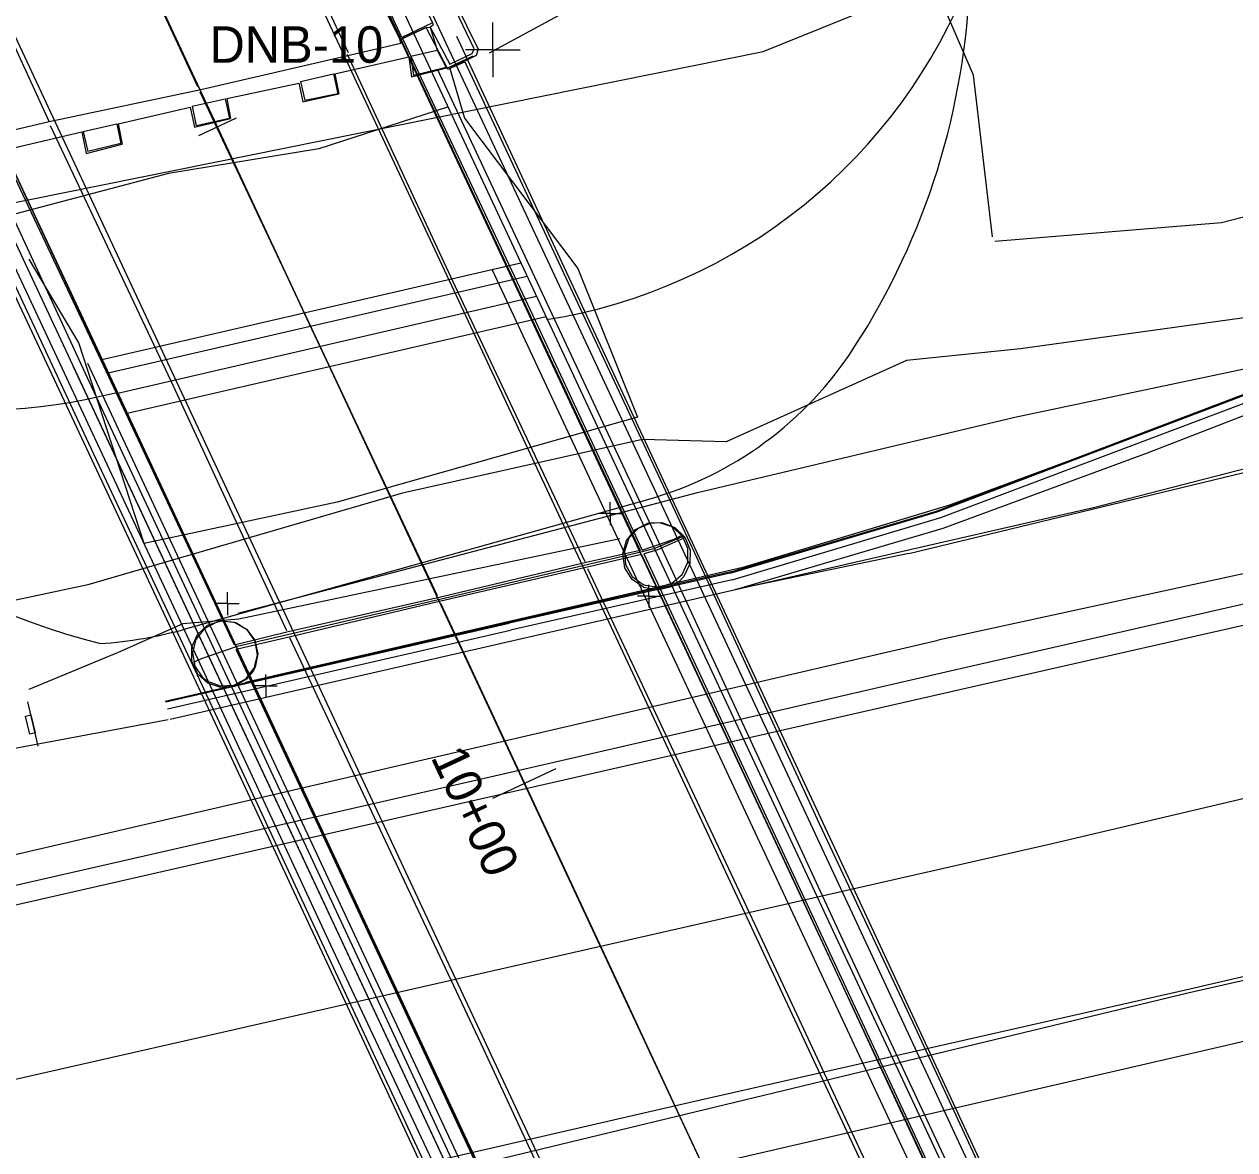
# Model space of a CAD drawing. Extents: x 1040567 to 1041254, y 1126791 to 1127594.
# Drawn here: x 1040909 to 1040992.5, y 1127190.9 to 1127268.5 of the extents above; entities that cross this region are included whole.
import ezdxf

# ---------------------------------------------------------------- set-up
doc = ezdxf.new("R2010")
doc.units = 0
for name, color, linetype in [('AC_P', 7, 'Continuous'), ('ACSR_P_T', 7, 'Continuous'), ('ACSRT_P', 7, 'Continuous'), ('BAJ', 7, 'Continuous'), ('BBR', 7, 'Continuous'), ('BBW_P', 7, 'Continuous'), ('BCLBRG_P', 7, 'Continuous'), ('BDE', 7, 'Continuous'), ('BDE_P', 7, 'Continuous'), ('BDET_P', 7, 'Continuous'), ('BDSW', 7, 'Continuous'), ('BF', 7, 'Continuous'), ('BFNC', 7, 'Continuous'), ('BPED', 7, 'Continuous'), ('BR', 7, 'Continuous'), ('BSE', 7, 'Continuous'), ('BSUBM', 7, 'Continuous'), ('BWI', 7, 'Continuous'), ('BWW', 7, 'Continuous'), ('EWFG', 7, 'Continuous'), ('GDH_C', 7, 'Continuous'), ('LARR', 7, 'Continuous'), ('LELB', 7, 'Continuous'), ('LELB_P', 7, 'Continuous'), ('LFILL_P', 7, 'Continuous'), ('LFNC', 7, 'Continuous'), ('LUKL', 7, 'Continuous'), ('PE', 7, 'Continuous'), ('PE_P', 7, 'Continuous'), ('PET', 7, 'Continuous'), ('PET_P', 7, 'Continuous'), ('RBS_P', 7, 'Continuous'), ('RELB', 7, 'Continuous'), ('RGB', 7, 'Continuous'), ('RGB_P', 7, 'Continuous'), ('RGCB_P', 7, 'Continuous'), ('RSW', 7, 'Continuous'), ('SDEL', 7, 'Continuous'), ('STBW', 7, 'Continuous'), ('STFBY', 7, 'Continuous'), ('STFBY_P', 7, 'Continuous'), ('STSEW', 7, 'Continuous'), ('STSEY', 7, 'Continuous'), ('UFO', 7, 'Continuous')]:
    doc.layers.add(name, color=color, linetype=linetype)

msp = doc.modelspace()

# ---------------------------------------------------------------- linework, layer by layer
at = {"layer": 'AC_P'}
msp.add_line((1040885.873, 1127339.474), (1041008.875, 1127076.161), dxfattribs=at)
at = {"layer": 'ACSRT_P'}
for points in [[(1040923.639, 1127262.029), (1040921.03, 1127260.811)], [(1040945.67, 1127217.135), (1040941.321, 1127215.103)]]:
    msp.add_lwpolyline(points, dxfattribs=at)
at = {"layer": 'BAJ'}
for points in [[(1040905.702, 1127259.405), (1040905.285, 1127260.055), (1040907.003, 1127260.795), (1040907.109, 1127260.952), (1040910.735, 1127261.792), (1040921.202, 1127263.997), (1040934.992, 1127267.213), (1040934.925, 1127267.48), (1040934.978, 1127267.518), (1040935.099, 1127267.531), (1040936.751, 1127268.274), (1040937.018, 1127268.3), (1040937.496, 1127266.727)], [(1040951.593, 1127231.935), (1040947.948, 1127231.086), (1040937.753, 1127228.696), (1040927.384, 1127226.251), (1040923.736, 1127225.397)], [(1040951.486, 1127232.196), (1040947.775, 1127231.371), (1040937.644, 1127228.969), (1040927.22, 1127226.59)], [(1040927.22, 1127226.59), (1040923.588, 1127225.694)]]:
    msp.add_lwpolyline(points, dxfattribs=at)
at = {"layer": 'BBR'}
for points in [[(1041019.719, 1127088.654), (1041004.406, 1127121.53), (1041003.585, 1127123.404), (1040990.693, 1127150.999), (1040979.268, 1127175.742), (1040977.886, 1127178.782), (1040965.491, 1127205.307), (1040953.611, 1127231.003), (1040952.138, 1127234.156), (1040937.531, 1127265.417)], [(1040989.084, 1127081.358), (1040979.685, 1127101.678), (1040973.812, 1127114.274), (1040972.939, 1127116.09), (1040958.781, 1127146.714), (1040948.043, 1127169.603), (1040947.215, 1127171.406), (1040934.066, 1127199.748), (1040923.012, 1127223.473), (1040921.387, 1127226.985), (1040913.364, 1127244.169), (1040907.222, 1127257.388)]]:
    msp.add_lwpolyline(points, dxfattribs=at)
at = {"layer": 'BBW_P'}
for p, q in [((1040943.277, 1127252.03), (1040914.384, 1127245.36)), ((1040943.709, 1127251.103), (1040914.817, 1127244.433))]:
    msp.add_line(p, q, dxfattribs=at)
at = {"layer": 'BCLBRG_P'}
msp.add_line((1040944.354, 1127249.723), (1040915.47, 1127243.035), dxfattribs=at)
at = {"layer": 'BDE'}
for points in [[(1040939.415, 1127265.922), (1040947.859, 1127247.808), (1040955.236, 1127232.05), (1040963.843, 1127213.367), (1040970.466, 1127199.289), (1040979.576, 1127179.6), (1040988.925, 1127159.501), (1040997.881, 1127140.234), (1041005.324, 1127124.249), (1041014.183, 1127105.141), (1041021.331, 1127089.904)], [(1040905.131, 1127257.422), (1040913.466, 1127239.609), (1040920.648, 1127224.278), (1040933.375, 1127196.889), (1040945.375, 1127171.145), (1040955.293, 1127149.679), (1040963.856, 1127131.323), (1040972.311, 1127113.367), (1040978.963, 1127098.619), (1040987.061, 1127081.333)]]:
    msp.add_lwpolyline(points, dxfattribs=at)
at = {"layer": 'BDE_P'}
msp.add_line((1040912.39, 1127244.904), (1040982.54, 1127094.731), dxfattribs=at)
at = {"layer": 'BDET_P'}
for p, q in [((1040941.284, 1127251.57), (1041011.459, 1127101.345)), ((1040914.383, 1127245.364), (1040984.534, 1127095.188))]:
    msp.add_line(p, q, dxfattribs=at)
at = {"layer": 'BDSW'}
for points in [[(1040930.029, 1127283.497), (1040927.918, 1127282.446), (1040934.978, 1127267.518)], [(1040923.588, 1127225.694), (1040914.762, 1127244.63), (1040907.109, 1127260.952), (1040899.625, 1127276.933)], [(1040938.228, 1127265.419), (1040936.751, 1127268.274), (1040935.099, 1127267.531), (1040944.282, 1127248.014), (1040951.626, 1127232.223), (1040953.838, 1127232.99), (1040954.435, 1127233.274), (1040954.508, 1127233.062), (1040952.645, 1127232.223), (1040951.738, 1127231.963), (1040962.689, 1127208.469), (1040977.373, 1127176.939), (1040979.827, 1127177.801), (1040980.125, 1127177.936)], [(1040934.978, 1127267.518), (1040944.109, 1127247.97), (1040951.486, 1127232.196)], [(1040938.228, 1127265.419), (1040939.415, 1127265.922)], [(1040907.003, 1127260.795), (1040914.479, 1127244.931), (1040923.49, 1127225.691)], [(1040951.593, 1127231.935), (1040962.526, 1127208.475), (1040977.201, 1127176.865)], [(1040923.626, 1127225.384), (1040937.857, 1127194.844), (1040949.201, 1127170.502)], [(1040949.268, 1127170.586), (1040934.086, 1127203.088), (1040923.736, 1127225.397)]]:
    msp.add_lwpolyline(points, dxfattribs=at)
at = {"layer": 'BF'}
for points in [[(1040930.453, 1127265.089), (1040935.535, 1127266.251)], [(1040935.535, 1127266.251), (1040935.738, 1127264.89), (1040938.318, 1127265.552), (1040939.988, 1127266.321)], [(1040922.991, 1127263.375), (1040927.958, 1127264.448)], [(1040927.958, 1127264.448), (1040928.234, 1127263.152), (1040930.723, 1127263.706)], [(1040930.453, 1127265.089), (1040930.723, 1127263.706)], [(1040915.502, 1127261.647), (1040920.465, 1127262.786)], [(1040920.465, 1127262.786), (1040920.771, 1127261.413), (1040923.258, 1127262.002)], [(1040922.991, 1127263.375), (1040923.258, 1127262.002)], [(1040908.014, 1127259.919), (1040913, 1127261.082)], [(1040913, 1127261.082), (1040913.293, 1127259.598)], [(1040915.502, 1127261.647), (1040915.779, 1127260.224)], [(1040913.293, 1127259.598), (1040915.779, 1127260.224)]]:
    msp.add_lwpolyline(points, dxfattribs=at)
at = {"layer": 'BFNC'}
for points in [[(1041029.028, 1127072.099), (1041018.346, 1127094.834), (1041008.209, 1127116.584), (1040997.724, 1127139.118), (1040988.217, 1127159.54), (1040977.754, 1127182.181), (1040967.557, 1127204.106), (1040957.206, 1127226.328), (1040946.955, 1127248.298), (1040937.324, 1127268.899), (1040930.675, 1127283.065)], [(1040995.864, 1127064.064), (1040985.169, 1127086.964), (1040974.401, 1127110.108), (1040963.406, 1127133.965), (1040952.032, 1127157.995), (1040940.832, 1127182.3), (1040930.319, 1127204.627), (1040919.348, 1127228.3), (1040907.363, 1127253.93), (1040897.309, 1127275.145)]]:
    msp.add_lwpolyline(points, dxfattribs=at)
at = {"layer": 'BPED'}
for points in [[(1040935.678, 1127266.306), (1040937.496, 1127266.727)], [(1040935.678, 1127266.306), (1040935.863, 1127264.96)], [(1040937.496, 1127266.727), (1040938.118, 1127265.526)], [(1040938.118, 1127265.526), (1040935.863, 1127264.96)], [(1040928.083, 1127264.556), (1040930.353, 1127265.079)], [(1040928.083, 1127264.556), (1040928.375, 1127263.246)], [(1040930.353, 1127265.079), (1040930.646, 1127263.713)], [(1040930.646, 1127263.713), (1040928.375, 1127263.246)], [(1040920.603, 1127262.845), (1040922.89, 1127263.363)], [(1040920.603, 1127262.845), (1040920.879, 1127261.489)], [(1040922.89, 1127263.363), (1040923.189, 1127262.013)], [(1040923.189, 1127262.013), (1040920.879, 1127261.489)], [(1040913.096, 1127261.111), (1040915.401, 1127261.641)], [(1040913.096, 1127261.111), (1040913.416, 1127259.734)], [(1040915.401, 1127261.641), (1040915.681, 1127260.274)], [(1040915.681, 1127260.274), (1040913.416, 1127259.734)]]:
    msp.add_lwpolyline(points, dxfattribs=at)
at = {"layer": 'BR'}
for points in [[(1040938.828, 1127267.695), (1040955.714, 1127231.414), (1040967.747, 1127205.578), (1040979.747, 1127179.699), (1040993.173, 1127150.575), (1041022.323, 1127088.276)], [(1040904.042, 1127259.025), (1040921.201, 1127222.4), (1040933.244, 1127196.591), (1040950.275, 1127159.967), (1040963.843, 1127130.88), (1040975.411, 1127105.881), (1040987.575, 1127079.658)]]:
    msp.add_lwpolyline(points, dxfattribs=at)
at = {"layer": 'BSE'}
msp.add_line((1040945.008, 1127248.324), (1040916.115, 1127241.654), dxfattribs=at)
for points in [[(1040952.227, 1127234.083), (1040951.358, 1127233.728), (1040950.713, 1127233.047), (1040950.406, 1127232.161), (1040950.492, 1127231.227), (1040950.954, 1127230.411), (1040951.712, 1127229.859), (1040951.852, 1127229.803), (1040952.781, 1127229.674), (1040953.681, 1127229.94), (1040954.39, 1127230.554), (1040954.784, 1127231.405), (1040954.792, 1127232.343), (1040954.413, 1127233.2), (1040953.714, 1127233.826), (1040952.819, 1127234.107), (1040952.227, 1127234.083)], [(1040922.264, 1127227.241), (1040921.429, 1127226.802), (1040920.848, 1127226.06), (1040920.623, 1127225.144), (1040920.793, 1127224.217), (1040921.328, 1127223.44), (1040921.65, 1127223.188), (1040922.532, 1127222.854), (1040923.473, 1127222.912), (1040924.308, 1127223.35), (1040924.89, 1127224.092), (1040925.116, 1127225.007), (1040924.946, 1127225.935), (1040924.412, 1127226.711), (1040923.605, 1127227.2), (1040922.669, 1127227.315), (1040922.264, 1127227.241)]]:
    msp.add_lwpolyline(points, dxfattribs=at)
at = {"layer": 'BSUBM'}
for points in [[(1040951.17, 1127233.642), (1040952.028, 1127234.079), (1040952.989, 1127234.134), (1040953.892, 1127233.797), (1040954.582, 1127233.126), (1040954.945, 1127232.234), (1040954.918, 1127231.272), (1040954.507, 1127230.401), (1040954.134, 1127230.013), (1040954.134, 1127230.013), (1040953.624, 1127229.691), (1040952.686, 1127229.474), (1040951.74, 1127229.653), (1040950.946, 1127230.198), (1040950.438, 1127231.016), (1040950.301, 1127231.969), (1040950.56, 1127232.896), (1040951.17, 1127233.642)], [(1040921.668, 1127227.04), (1040922.575, 1127227.341), (1040923.525, 1127227.249), (1040924.357, 1127226.779), (1040924.927, 1127226.013), (1040925.138, 1127225.081), (1040924.953, 1127224.144), (1040924.838, 1127223.912), (1040924.838, 1127223.912), (1040924.362, 1127223.324), (1040923.532, 1127222.852), (1040922.581, 1127222.757), (1040921.674, 1127223.055), (1040920.965, 1127223.696), (1040920.577, 1127224.568), (1040920.575, 1127225.523), (1040920.961, 1127226.397), (1040921.668, 1127227.04)]]:
    msp.add_lwpolyline(points, dxfattribs=at)
at = {"layer": 'BWI'}
for p, q in [((1040949.436, 1127234.746), (1040949.436, 1127235.533)), ((1040949.436, 1127234.746), (1040948.648, 1127234.746)), ((1040949.436, 1127234.746), (1040950.223, 1127234.746)), ((1040949.436, 1127234.746), (1040949.436, 1127233.958)), ((1040923.052, 1127228.538), (1040923.052, 1127229.326)), ((1040952.092, 1127229.048), (1040952.092, 1127229.836)), ((1040923.052, 1127228.538), (1040922.264, 1127228.538)), ((1040923.052, 1127228.538), (1040923.839, 1127228.538)), ((1040923.052, 1127228.538), (1040923.052, 1127227.751)), ((1040952.092, 1127229.048), (1040951.304, 1127229.048)), ((1040952.092, 1127229.048), (1040952.879, 1127229.048)), ((1040952.092, 1127229.048), (1040952.092, 1127228.261)), ((1040925.687, 1127222.871), (1040925.687, 1127223.658)), ((1040925.687, 1127222.871), (1040924.9, 1127222.871)), ((1040925.687, 1127222.871), (1040926.474, 1127222.871)), ((1040925.687, 1127222.871), (1040925.687, 1127222.083))]:
    msp.add_line(p, q, dxfattribs=at)
at = {"layer": 'BWW'}
for points in [[(1040930.029, 1127283.497), (1040931.878, 1127284.254), (1040937.123, 1127273.299), (1040940.332, 1127266.78), (1040940.197, 1127266.354), (1040938.378, 1127265.457)], [(1040931.757, 1127284.17), (1040930.207, 1127283.352), (1040937.177, 1127268.6), (1040937.232, 1127268.435), (1040937.018, 1127268.3), (1040938.371, 1127265.752), (1040939.918, 1127266.487), (1040940.06, 1127266.807), (1040931.757, 1127284.17)]]:
    msp.add_lwpolyline(points, dxfattribs=at)
at = {"layer": 'EWFG'}
for q in [(1040941.342, 1127268.638), (1040939.458, 1127266.75), (1040941.348, 1127264.861), (1040943.233, 1127266.75)]:
    msp.add_line((1040941.345, 1127266.75), q, dxfattribs=at)
at = {"layer": 'LARR'}
msp.add_lwpolyline([(1040938.378, 1127265.457), (1040939.386, 1127262.039), (1040947.199, 1127251.656), (1040951.312, 1127241.39), (1040930.595, 1127235.541), (1040917.305, 1127232.695), (1040912.789, 1127246.533), (1040909.374, 1127252.299)], dxfattribs=at)
at = {"layer": 'LELB'}
for points in [[(1041036.754, 1127304.812), (1041041.911, 1127288.129), (1041039.583, 1127268.559), (1041014.915, 1127260.842), (1040991.59, 1127254.796), (1040975.943, 1127253.515)], [(1040975.789, 1127253.83), (1040974.471, 1127264.983), (1040969.762, 1127275.892)], [(1040938.219, 1127262.787), (1040929.338, 1127259.921), (1040918.98, 1127258.199), (1040908.109, 1127255.326)], [(1040998.299, 1127248.977), (1040977.716, 1127246.115), (1040969.851, 1127245.317), (1040957.43, 1127239.695), (1040951.648, 1127239.862), (1040935.113, 1127236.151), (1040913.4, 1127229.831), (1040900.228, 1127227.021), (1040866.66, 1127219.31)], [(1040923.779, 1127227.874), (1040955.444, 1127236.193), (1040977.337, 1127241.397), (1040999.697, 1127246.116)], [(1040950.094, 1127233.006), (1040923.82, 1127227.461), (1040919.961, 1127227.131), (1040915.499, 1127225.164), (1040909.343, 1127222.621)]]:
    msp.add_lwpolyline(points, dxfattribs=at)
at = {"layer": 'LELB_P'}
for centre, radius, start, end in [((1040939.068, 1127285.398), 37.742, 279.10183, 338.82853), ((1040905.241, 1127283.652), 41.804, 237.40306, 284.11468)]:
    msp.add_arc(centre, radius, start, end, dxfattribs=at)
at = {"layer": 'LFILL_P'}
msp.add_line((1040920.151, 1127226.791), (1040952.023, 1127235.721), dxfattribs=at)
for centre, radius, start, end in [((1040924.259, 1127273.342), 50, 327.14773, 358.19607), ((1040927.727, 1127277.827), 53.755, 213.14797, 255.51846), ((1040945.287, 1127259.763), 24.968, 285.65095, 327.14773), ((1040912.297, 1127254.826), 29.114, 273.91396, 285.65095)]:
    msp.add_arc(centre, radius, start, end, dxfattribs=at)
at = {"layer": 'LFNC'}
msp.add_lwpolyline([(1040941.117, 1127266.524), (1040958.176, 1127275.811), (1040968.755, 1127281.542), (1041010.053, 1127295.832), (1041036.486, 1127309.717), (1041060.647, 1127319.426), (1041072.109, 1127323.179)], dxfattribs=at)
at = {"layer": 'LUKL'}
msp.add_lwpolyline([(1040954.464, 1127233.175), (1040952.44, 1127232.323), (1040951.538, 1127232.075), (1040937.678, 1127228.822), (1040923.701, 1127225.571), (1040921.231, 1127224.727), (1040920.687, 1127224.482)], dxfattribs=at)
at = {"layer": 'PE'}
for points in [[(1040847.432, 1127447.269), (1040868.403, 1127402.853), (1040889.603, 1127357.481), (1040910.994, 1127312.252), (1040921.836, 1127289.558), (1040927.608, 1127281.921), (1040934.925, 1127267.48)], [(1040934.925, 1127267.48), (1040934.992, 1127267.213)], [(1040970.03, 1127231.987), (1040995.878, 1127238.254), (1041022.554, 1127245.488), (1041051.834, 1127252.702), (1041099.433, 1127263.824)], [(1040970.03, 1127231.987), (1040958.081, 1127229.522)], [(1040990.943, 1127197.845), (1041038.944, 1127209.006), (1041086.518, 1127219.94), (1041116.437, 1127226.89)], [(1040918.956, 1127220.517), (1040889.792, 1127215.065), (1040861.88, 1127209.084), (1040835.083, 1127203.242), (1040808.72, 1127197.171), (1040782.996, 1127191.165)], [(1040956.515, 1127189.886), (1040990.943, 1127197.845)]]:
    msp.add_lwpolyline(points, dxfattribs=at)
at = {"layer": 'PE_P'}
for points in [[(1040916.887, 1127306.161), (1041021.781, 1127081.611), (1041023.896, 1127077.084), (1041026.013, 1127072.558), (1041028.13, 1127068.033), (1041030.249, 1127063.508), (1041032.369, 1127058.983), (1041034.49, 1127054.459), (1041036.612, 1127049.936), (1041037.879, 1127047.236)], [(1040891.518, 1127294.31), (1040996.412, 1127069.76), (1040998.531, 1127065.227), (1041000.65, 1127060.695), (1041002.771, 1127056.163), (1041004.893, 1127051.631), (1041007.015, 1127047.1), (1041009.139, 1127042.57), (1041009.957, 1127040.827)]]:
    msp.add_lwpolyline(points, dxfattribs=at)
at = {"layer": 'PET'}
for points in [[(1040972.884, 1127223.9), (1040998.559, 1127229.771), (1041025.446, 1127235.79), (1041055.843, 1127242.968), (1041103.986, 1127253.934)], [(1040989.254, 1127201.677), (1041037.878, 1127212.709), (1041085.194, 1127223.891), (1041114.704, 1127230.653)], [(1040941.963, 1127216.771), (1040972.884, 1127223.9)], [(1040898.454, 1127206.84), (1040941.963, 1127216.771)], [(1040908.8, 1127182.265), (1040989.254, 1127201.677)]]:
    msp.add_lwpolyline(points, dxfattribs=at)
at = {"layer": 'PET_P'}
for points in [[(1040894.933, 1127343.706), (1041018.157, 1127079.918), (1041020.272, 1127075.391), (1041022.389, 1127070.864), (1041024.507, 1127066.337), (1041026.627, 1127061.811), (1041028.747, 1127057.286), (1041030.868, 1127052.761), (1041032.991, 1127048.237), (1041035.115, 1127043.713)], [(1040876.813, 1127335.242), (1041000.036, 1127071.453), (1041002.154, 1127066.921), (1041004.273, 1127062.389), (1041006.394, 1127057.858), (1041008.515, 1127053.328), (1041010.637, 1127048.798), (1041012.761, 1127044.269)]]:
    msp.add_lwpolyline(points, dxfattribs=at)
at = {"layer": 'RBS_P'}
for points in [[(1040917.793, 1127306.584), (1041022.687, 1127082.034), (1041024.802, 1127077.508), (1041026.919, 1127072.982), (1041029.036, 1127068.456), (1041031.155, 1127063.931), (1041033.275, 1127059.407), (1041035.396, 1127054.883), (1041037.518, 1127050.359), (1041038.785, 1127047.66)], [(1040889.729, 1127293.414), (1040994.601, 1127068.913), (1040996.719, 1127064.38), (1040998.839, 1127059.847), (1041000.959, 1127055.315), (1041003.081, 1127050.783), (1041005.204, 1127046.252), (1041007.329, 1127041.721), (1041008.147, 1127039.977)]]:
    msp.add_lwpolyline(points, dxfattribs=at)
at = {"layer": 'RELB'}
for points in [[(1041103.151, 1127255.748), (1041074.681, 1127249.139), (1041023.206, 1127237.156), (1040972.045, 1127226.01)], [(1040919.095, 1127220.574), (1040958.081, 1127229.522), (1040972.401, 1127233.746), (1040986.481, 1127238.933), (1041000.52, 1127244.4), (1041000.042, 1127245.569), (1040986.861, 1127240.532), (1040972.833, 1127235.332), (1040958.573, 1127231.028), (1040924.279, 1127223.087)], [(1040957.698, 1127230.638), (1040971.985, 1127234.864), (1040999.993, 1127245.511), (1041000.157, 1127245.021)], [(1040957.746, 1127230.737), (1040971.937, 1127234.904), (1041000.011, 1127245.605)], [(1040957.838, 1127230.189), (1040972.235, 1127234.468), (1041000.157, 1127245.021)], [(1040957.698, 1127230.638), (1040942.463, 1127227.177)], [(1040957.838, 1127230.189), (1040942.557, 1127226.699)], [(1040957.746, 1127230.737), (1040942.562, 1127227.291)], [(1040918.736, 1127221.798), (1040942.562, 1127227.291)], [(1040918.783, 1127221.766), (1040942.463, 1127227.177)], [(1040897.681, 1127208.755), (1040972.045, 1127226.01)], [(1040918.899, 1127221.282), (1040942.557, 1127226.699)]]:
    msp.add_lwpolyline(points, dxfattribs=at)
at = {"layer": 'RGB'}
msp.add_lwpolyline([(1040958.081, 1127229.522), (1040982.838, 1127235.199), (1041000.253, 1127239.669)], dxfattribs=at)
at = {"layer": 'RGB_P'}
for points in [[(1040903.462, 1127339.624), (1040916.887, 1127306.161), (1040942.28, 1127251.8)], [(1040874.47, 1127326.081), (1040891.518, 1127294.31), (1040914.292, 1127245.557)]]:
    msp.add_lwpolyline(points, dxfattribs=at)
at = {"layer": 'RGCB_P'}
for p, q in [((1040942.28, 1127251.8), (1041012.456, 1127101.573)), ((1040913.386, 1127245.134), (1040983.609, 1127094.742))]:
    msp.add_line(p, q, dxfattribs=at)
at = {"layer": 'RSW'}
msp.add_lwpolyline([(1040937.177, 1127268.6), (1040935.058, 1127267.595), (1040931.57, 1127275.165), (1040928.089, 1127282.329), (1040930.023, 1127283.379), (1040933.514, 1127276.082), (1040937.177, 1127268.6)], dxfattribs=at)
at = {"layer": 'SDEL'}
msp.add_line((1040909.99, 1127218.707), (1040909.266, 1127221.772), dxfattribs=at)
msp.add_lwpolyline([(1040909.482, 1127220.858), (1040909.774, 1127219.622), (1040909.403, 1127219.534), (1040909.111, 1127220.77)], close=True, dxfattribs=at)
at = {"layer": 'STBW'}
for points in [[(1040979.909, 1127211.982), (1041003.006, 1127217.443), (1041028.656, 1127223.514), (1041058.653, 1127230.065), (1041109.541, 1127241.869)], [(1040900.515, 1127193.942), (1040979.909, 1127211.982)]]:
    msp.add_lwpolyline(points, dxfattribs=at)
at = {"layer": 'STFBY'}
for points in [[(1040921.003, 1127264.184), (1040900.774, 1127307.659), (1040879.59, 1127352.837), (1040858.451, 1127397.834), (1040837.328, 1127442.455)], [(1040937.518, 1127229.085), (1040928.812, 1127247.598), (1040921.15, 1127263.826)], [(1040963.268, 1127173.717), (1040950.169, 1127201.941), (1040937.747, 1127228.54)]]:
    msp.add_lwpolyline(points, dxfattribs=at)
at = {"layer": 'STFBY_P'}
msp.add_lwpolyline([(1040907.521, 1127293.131), (1040909.637, 1127288.601), (1040911.753, 1127284.071), (1040913.87, 1127279.54), (1040915.986, 1127275.01), (1040918.102, 1127270.48), (1040920.218, 1127265.95), (1040922.334, 1127261.42), (1040924.45, 1127256.89), (1040926.567, 1127252.36), (1040928.683, 1127247.83), (1040930.799, 1127243.3), (1040932.915, 1127238.769), (1040935.031, 1127234.239), (1040937.147, 1127229.709), (1040939.263, 1127225.179), (1040941.38, 1127220.649), (1040943.496, 1127216.119), (1040945.612, 1127211.589), (1040947.728, 1127207.059), (1040949.844, 1127202.529), (1040951.96, 1127197.998), (1040954.077, 1127193.468), (1040956.193, 1127188.938)], dxfattribs=at)
at = {"layer": 'STSEW'}
for points in [[(1040846.591, 1127446.868), (1040867.569, 1127402.434), (1040888.892, 1127357.152), (1040910.22, 1127311.846), (1040931.356, 1127266.563)], [(1040910.735, 1127261.792), (1040891.458, 1127303.918), (1040870.368, 1127348.699), (1040849.019, 1127393.894), (1040828.274, 1127438.142)], [(1040947.694, 1127231.43), (1040938.75, 1127250.446), (1040931.325, 1127266.422)], [(1040927.13, 1127226.658), (1040919.15, 1127243.888), (1040910.833, 1127261.504)], [(1040973.545, 1127222.617), (1040998.842, 1127228.362), (1041025.914, 1127234.56), (1041056.184, 1127241.596), (1041104.55, 1127252.711)], [(1040973.544, 1127176.095), (1040959.771, 1127205.651), (1040947.896, 1127230.933)], [(1040952.919, 1127171.435), (1040940.716, 1127197.775), (1040927.348, 1127226.167)], [(1040942.291, 1127215.48), (1040973.545, 1127222.617)], [(1040898.339, 1127205.457), (1040942.291, 1127215.48)]]:
    msp.add_lwpolyline(points, dxfattribs=at)
at = {"layer": 'STSEY'}
for points in [[(1040989.11, 1127201.884), (1041037.72, 1127213.155), (1041085.111, 1127224.247), (1041114.543, 1127231.002)], [(1040955.148, 1127194.178), (1040989.11, 1127201.884)], [(1040908.934, 1127183.539), (1040955.148, 1127194.178)]]:
    msp.add_lwpolyline(points, dxfattribs=at)
at = {"layer": 'UFO'}
msp.add_lwpolyline([(1040764.749, 1127230.792), (1040862.999, 1127250.197), (1040889.009, 1127252.294), (1040959.971, 1127266.63), (1041031.497, 1127295.507), (1041079.551, 1127307.013)], dxfattribs=at)

# ---------------------------------------------------------------- texts
at = {"layer": 'ACSR_P_T'}
msp.add_text('10+00', height=2.496, rotation=295.03874, dxfattribs=at).set_placement((1040937.022, 1127217.955))
at = {"layer": 'GDH_C'}
msp.add_text('DNB-10', height=2.5197, rotation=360, dxfattribs=at).set_placement((1040921.801, 1127265.847))

doc.saveas('drawing.dxf')
